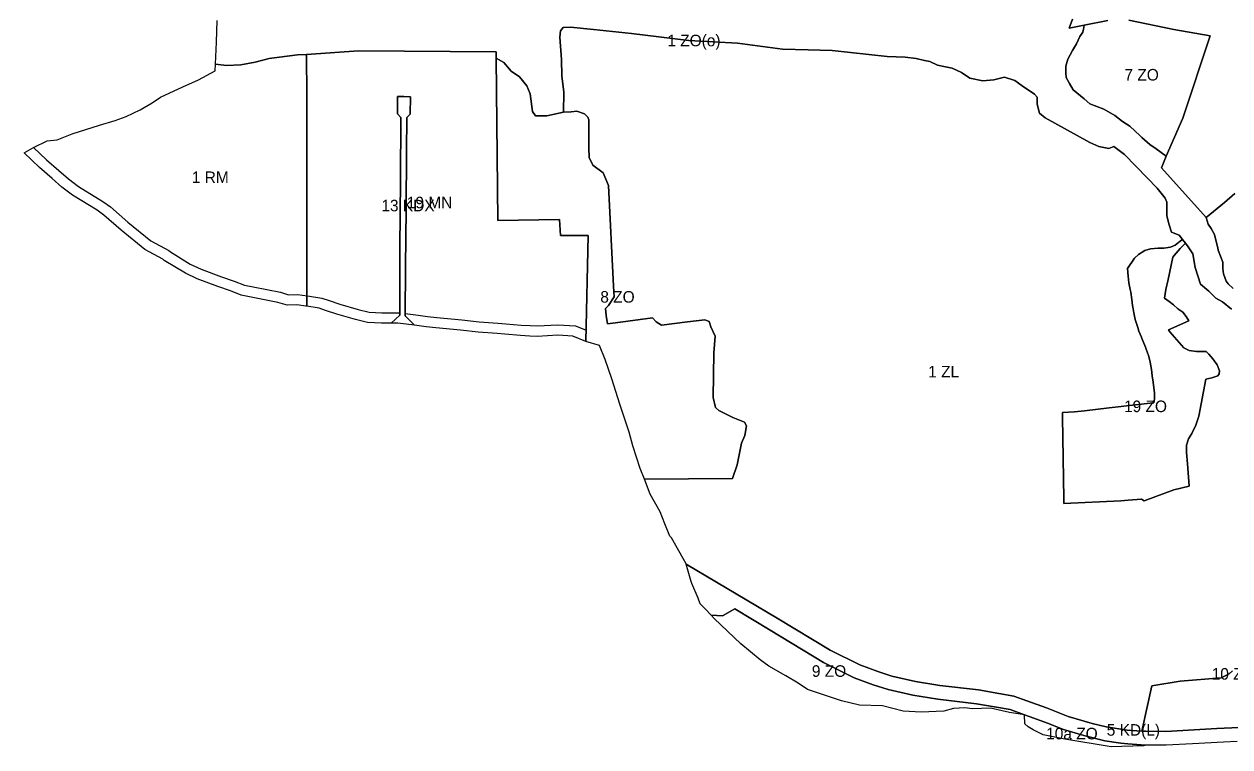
# Model space of a CAD drawing. Extents: x 7418056 to 7420315, y 5537846 to 5539505.
# Drawn here: x 7418283 to 7419326, y 5537849 to 5538474 of the extents above; entities that cross this region are included whole.
import ezdxf

# ---------------------------------------------------------------- set-up
doc = ezdxf.new("R2010")
doc.units = 0
for name, color, linetype in [('linie_rozgraniczajace', 7, 'Continuous'), ('linie_zabudowy_nieprzekraczalne', 7, 'Continuous'), ('oznaczenia_przeznaczen', 7, 'Continuous')]:
    doc.layers.add(name, color=color, linetype=linetype)

msp = doc.modelspace()

# ---------------------------------------------------------------- linework, layer by layer
at = {"layer": 'linie_rozgraniczajace'}
for points in [[(7418448.73, 5538439.82), (7418449.78, 5538458.94), (7418450.38, 5538477.48)], [(7419190.15, 5538478.7), (7419187.23, 5538471.09), (7419200.36, 5538473.67), (7419199.78, 5538469.97), (7419199.04, 5538467.44), (7419196.49, 5538463.7), (7419193.79, 5538457.39), (7419190.18, 5538451.63), (7419186.05, 5538444.07), (7419184.52, 5538438.1), (7419184.45, 5538432.48), (7419184.62, 5538428.34), (7419187.49, 5538423.15), (7419190.67, 5538417.66), (7419200.24, 5538409.93), (7419205.16, 5538405.41), (7419217.18, 5538400.86), (7419226.87, 5538395.35), (7419233.58, 5538390.3), (7419239.66, 5538386.11), (7419248.87, 5538377.92), (7419250.11, 5538376.49), (7419257.09, 5538370.36), (7419262.46, 5538366.49), (7419271.11, 5538360.17), (7419267.32, 5538350.24), (7419305.83, 5538307.27), (7419307.65, 5538301.56), (7419310.18, 5538297.82), (7419313.05, 5538292.61), (7419314.48, 5538286.46), (7419315.89, 5538280.9), (7419316.27, 5538278.85), (7419318.24, 5538273.9), (7419320.23, 5538268.66), (7419320.17, 5538263.04)], [(7419238.97, 5538477.94), (7419277.73, 5538469.82), (7419309.41, 5538464.3), (7419285.58, 5538393.04), (7419271.11, 5538360.17), (7419262.46, 5538366.49), (7419257.09, 5538370.36), (7419250.11, 5538376.49), (7419248.87, 5538377.92), (7419239.66, 5538386.11), (7419233.58, 5538390.3), (7419226.87, 5538395.35), (7419217.18, 5538400.86), (7419205.16, 5538405.41), (7419200.24, 5538409.93), (7419190.67, 5538417.66), (7419187.49, 5538423.15), (7419184.62, 5538428.34), (7419184.45, 5538432.48), (7419184.52, 5538438.1), (7419186.05, 5538444.07), (7419190.18, 5538451.63), (7419193.79, 5538457.39), (7419196.49, 5538463.7), (7419199.04, 5538467.44), (7419199.78, 5538469.97), (7419200.36, 5538473.67), (7419220.85, 5538477.69)], [(7419220.85, 5538477.69), (7419200.36, 5538473.67), (7419187.23, 5538471.09), (7419190.15, 5538478.7)], [(7419330.63, 5538328.03), (7419321.67, 5538320.2), (7419305.83, 5538307.27), (7419267.32, 5538350.24), (7419271.11, 5538360.17), (7419285.58, 5538393.04), (7419309.41, 5538464.3), (7419277.73, 5538469.82), (7419238.97, 5538477.94)], [(7419221.52, 5538367.05), (7419213.03, 5538368.63), (7419205.29, 5538372.05), (7419166.47, 5538393.45), (7419161.72, 5538397.53), (7419159.55, 5538405.3), (7419159.77, 5538411.27), (7419157.24, 5538413.96), (7419146.58, 5538421.01), (7419140.28, 5538425.6), (7419131.34, 5538428.7), (7419122.11, 5538426.27), (7419112.52, 5538425.49), (7419101.32, 5538427.87), (7419094.06, 5538432.58), (7419086.14, 5538436.39), (7419078.82, 5538437.85), (7419073.38, 5538438.91), (7419066.88, 5538442.18), (7419062.24, 5538443.04), (7419054.98, 5538444.74), (7419045.35, 5538445.95), (7419029.75, 5538446.52), (7418982.41, 5538451.77), (7418961.63, 5538452.13), (7418939.46, 5538452.92), (7418900.31, 5538458.03), (7418858.23, 5538460.21), (7418808.59, 5538466.36), (7418775.81, 5538469.78), (7418756.06, 5538471.84), (7418749.6, 5538471.58), (7418747.34, 5538468.55), (7418746.66, 5538463.07), (7418748.22, 5538443.91), (7418748.45, 5538429.86), (7418750.22, 5538415.52), (7418749.97, 5538398.36), (7418735.34, 5538395.21), (7418725.7, 5538395.27), (7418723.06, 5538399.02), (7418720.98, 5538414.29), (7418718.19, 5538421.18), (7418711.86, 5538428.95), (7418704.66, 5538433.66), (7418698.32, 5538441.42), (7418691.58, 5538445.1), (7418691.53, 5538450.4), (7418572.41, 5538451.25), (7418527.44, 5538448.19), (7418519.84, 5538447.96), (7418495.11, 5538444.7), (7418483.21, 5538441.7), (7418470.77, 5538439.19), (7418458.25, 5538438.69), (7418448.73, 5538439.82)], [(7418746.66, 5538463.07), (7418747.34, 5538468.55), (7418749.6, 5538471.58), (7418756.06, 5538471.84), (7418775.81, 5538469.78), (7418808.59, 5538466.36), (7418858.23, 5538460.21), (7418900.31, 5538458.03), (7418939.46, 5538452.92), (7418961.63, 5538452.13), (7418982.41, 5538451.77), (7419029.75, 5538446.52), (7419045.35, 5538445.95), (7419054.98, 5538444.74), (7419062.24, 5538443.04), (7419066.88, 5538442.18), (7419073.38, 5538438.91), (7419078.82, 5538437.85), (7419086.14, 5538436.39), (7419094.06, 5538432.58), (7419101.32, 5538427.87), (7419112.52, 5538425.49), (7419122.11, 5538426.27), (7419131.34, 5538428.7), (7419140.28, 5538425.6), (7419146.58, 5538421.01), (7419157.24, 5538413.96), (7419159.77, 5538411.27), (7419159.55, 5538405.3), (7419161.72, 5538397.53), (7419166.47, 5538393.45), (7419205.29, 5538372.05), (7419213.03, 5538368.63), (7419221.52, 5538367.05), (7419226.08, 5538368.5), (7419235.21, 5538361.66), (7419254.76, 5538341.44), (7419263.52, 5538332.51), (7419270.32, 5538323.95), (7419271.76, 5538320.37), (7419271.93, 5538308.59), (7419273.82, 5538301.01), (7419275.72, 5538294.7), (7419282.41, 5538291.89), (7419285.37, 5538288.17), (7419283.26, 5538286.72), (7419278.92, 5538283.32), (7419275.08, 5538281.53), (7419269.35, 5538280.71), (7419264.38, 5538280.76), (7419257.75, 5538280.26), (7419252.87, 5538278.73), (7419247.17, 5538275.23), (7419243.87, 5538272.1), (7419237.91, 5538263.27), (7419238.39, 5538256.42), (7419238.82, 5538250.61), (7419240.14, 5538245.02), (7419240.7, 5538242.61), (7419241.65, 5538236.35), (7419242.24, 5538231.09), (7419242.56, 5538228.3), (7419243.35, 5538224.67), (7419244.43, 5538219.03), (7419246.63, 5538212.24), (7419247.59, 5538208.86), (7419249.82, 5538203.89), (7419250.02, 5538203.45), (7419253.49, 5538195.02), (7419255.51, 5538189.42), (7419255.92, 5538188.3), (7419257.48, 5538182.03), (7419258.61, 5538175.84), (7419259.11, 5538170.36), (7419260.04, 5538164.92), (7419261.04, 5538155.35), (7419261.04, 5538150.49), (7419260.44, 5538146.94), (7419257.44, 5538146.79), (7419244.66, 5538145.2), (7419236.98, 5538144.24), (7419232.43, 5538143.73), (7419221.8, 5538142.53), (7419200.55, 5538140.14), (7419192.05, 5538139.18), (7419181.61, 5538138.61), (7419181.67, 5538134.61), (7419182.76, 5538063.87), (7419182.82, 5538059.86), (7419232.07, 5538062.32), (7419238.28, 5538062.68), (7419249.93, 5538063.78), (7419252.23, 5538062.14), (7419277.94, 5538071.77), (7419291.04, 5538074.98), (7419289.59, 5538094.23), (7419288.8, 5538104.14), (7419288.89, 5538110.32), (7419290.48, 5538115.86), (7419293.56, 5538120.49)], [(7418980.54, 5537932.96), (7418934.81, 5537960.77), (7418856.13, 5538007.51), (7418855.93, 5538007.87), (7418843.31, 5538030.31), (7418841.76, 5538031.54), (7418837.61, 5538042.43), (7418833.44, 5538052.58), (7418824.78, 5538067.93), (7418819.94, 5538080.93), (7418896.14, 5538081.39), (7418900.09, 5538093.38), (7418903.77, 5538112), (7418906.85, 5538118.69), (7418908.28, 5538127.08), (7418906.51, 5538130.29), (7418896.48, 5538134.27), (7418884.16, 5538140.34), (7418881.32, 5538142.96), (7418879.32, 5538151.64), (7418879.8, 5538190.33), (7418881.02, 5538204.49), (7418877.32, 5538212.73), (7418875.83, 5538217.29), (7418872.08, 5538218.62), (7418857.12, 5538217.1), (7418834.54, 5538214.14), (7418829.99, 5538216.91), (7418826.89, 5538220.48), (7418794.88, 5538216.13), (7418787.9, 5538215.2), (7418786.86, 5538222.55), (7418786.3, 5538228.4), (7418788.92, 5538231.24), (7418793.59, 5538238.56), (7418793.12, 5538247.99), (7418788.74, 5538334.83), (7418784.06, 5538345.73), (7418775.15, 5538352.39), (7418771.95, 5538359.16), (7418771.78, 5538367.42), (7418771.86, 5538391.74), (7418770.82, 5538394.04), (7418768.18, 5538396.8), (7418761.49, 5538399.16), (7418756.54, 5538398.63), (7418749.97, 5538398.36), (7418750.22, 5538415.52), (7418748.45, 5538429.86), (7418748.22, 5538443.91), (7418746.66, 5538463.07)], [(7419327.67, 5538227.89), (7419319.98, 5538234.34), (7419314.08, 5538237.53), (7419308.1, 5538243.54), (7419301.07, 5538249.51), (7419296.31, 5538263.91), (7419294.27, 5538275.81), (7419290.37, 5538281.91), (7419287.95, 5538284.94), (7419285.37, 5538288.17), (7419282.41, 5538291.89), (7419275.72, 5538294.7), (7419273.82, 5538301.01), (7419271.93, 5538308.59), (7419271.76, 5538320.37), (7419270.32, 5538323.95), (7419263.52, 5538332.51), (7419254.76, 5538341.44), (7419235.21, 5538361.66), (7419226.08, 5538368.5), (7419221.52, 5538367.05)], [(7419329.14, 5538245.97), (7419324.84, 5538249.93), (7419323.27, 5538252.23), (7419320.94, 5538258.64), (7419320.17, 5538263.04), (7419320.23, 5538268.66), (7419318.24, 5538273.9), (7419316.27, 5538278.85), (7419315.89, 5538280.9), (7419314.48, 5538286.46), (7419313.05, 5538292.61), (7419310.18, 5538297.82), (7419307.65, 5538301.56), (7419305.83, 5538307.27), (7419321.67, 5538320.2), (7419330.63, 5538328.03)], [(7419293.56, 5538120.49), (7419297.02, 5538127.53), (7419299.38, 5538135.36), (7419305.44, 5538167.57), (7419310.6, 5538168.61), (7419315.91, 5538170.23), (7419317.03, 5538172.03), (7419317.31, 5538174.54), (7419315.36, 5538179.93), (7419311.68, 5538184.88), (7419308.24, 5538189.11), (7419305.73, 5538191.44), (7419297.45, 5538191.37), (7419291.24, 5538192.26), (7419286.39, 5538194.41), (7419274.45, 5538208.49), (7419273.15, 5538210.02), (7419290.92, 5538217.99), (7419288.51, 5538221.7), (7419285.54, 5538225.34), (7419281.31, 5538228.15), (7419277.58, 5538231.66), (7419273.77, 5538234.64), (7419269.8, 5538237.44), (7419270.8, 5538245), (7419273.04, 5538253.69), (7419277.09, 5538272.99), (7419278.06, 5538274.52), (7419283.33, 5538280.54), (7419287.95, 5538284.94), (7419290.37, 5538281.91), (7419294.27, 5538275.81), (7419296.31, 5538263.91), (7419301.07, 5538249.51), (7419308.1, 5538243.54), (7419314.08, 5538237.53), (7419319.98, 5538234.34), (7419327.67, 5538227.89)], [(7419320.17, 5538263.04), (7419320.94, 5538258.64), (7419323.27, 5538252.23), (7419324.84, 5538249.93), (7419329.14, 5538245.97)], [(7419332.73, 5537854.1), (7419320.89, 5537853.5), (7419293.94, 5537852.05), (7419271.36, 5537850.8), (7419253.58, 5537850.83), (7419249.55, 5537851.13), (7419238.21, 5537851.93), (7419232, 5537852.69), (7419218.26, 5537854.66), (7419200, 5537859.2), (7419182.4, 5537864.47), (7419168.49, 5537870), (7419156.89, 5537874.27), (7419148.78, 5537877.11), (7419136.16, 5537881.67), (7419124.44, 5537883.87), (7419107.23, 5537886.75), (7419073.7, 5537890.67), (7419052.01, 5537894.29), (7419030.63, 5537898.97), (7419017.78, 5537903.17), (7419001.32, 5537909.25), (7418974.75, 5537922.44), (7418928.61, 5537950.49), (7418898.04, 5537968.75), (7418887.37, 5537962.66), (7418877.63, 5537963.36), (7418872.41, 5537968.93), (7418868.07, 5537973.15), (7418866.42, 5537978.03), (7418860.83, 5537990.68), (7418860.09, 5537993.34), (7418856.13, 5538007.51), (7418934.81, 5537960.77), (7418980.54, 5537932.96), (7419006.09, 5537920.29), (7419021.73, 5537914.51), (7419033.78, 5537910.55), (7419054.28, 5537906.07), (7419075.38, 5537902.54), (7419108.92, 5537898.63), (7419126.53, 5537895.68), (7419139.37, 5537893.28), (7419150.65, 5537889.13), (7419167.77, 5537883.21), (7419186.4, 5537875.79), (7419207.33, 5537869.53), (7419219.31, 5537866.63), (7419237.54, 5537864.01), (7419250.25, 5537863.11), (7419253.32, 5537862.89), (7419271.06, 5537862.8), (7419315.06, 5537865.23), (7419347.25, 5537866.84)], [(7419328.74, 5537915.33), (7419325.77, 5537912.5), (7419318.81, 5537909.18), (7419283.34, 5537906.26), (7419258.85, 5537902.17), (7419250.25, 5537863.11), (7419237.54, 5537864.01), (7419219.31, 5537866.63), (7419207.33, 5537869.53), (7419186.4, 5537875.79), (7419167.77, 5537883.21), (7419150.65, 5537889.13), (7419139.37, 5537893.28), (7419126.53, 5537895.68), (7419108.92, 5537898.63), (7419075.38, 5537902.54), (7419054.28, 5537906.07), (7419033.78, 5537910.55), (7419021.73, 5537914.51), (7419006.09, 5537920.29), (7418980.54, 5537932.96)], [(7419347.25, 5537866.84), (7419315.06, 5537865.23), (7419271.06, 5537862.8), (7419253.32, 5537862.89), (7419250.25, 5537863.11), (7419258.85, 5537902.17), (7419283.34, 5537906.26), (7419318.81, 5537909.18), (7419325.77, 5537912.5), (7419328.74, 5537915.33)]]:
    msp.add_lwpolyline(points, dxfattribs=at)
for points in [[(7418283.26, 5538363.1), (7418291.34, 5538367.72), (7418303.34, 5538373.67), (7418311.73, 5538374.28), (7418324.88, 5538379.67), (7418348.42, 5538387.19), (7418362.09, 5538390.99), (7418371.43, 5538394.67), (7418383.57, 5538400.46), (7418393.95, 5538406.53), (7418401.1, 5538411.22), (7418420.7, 5538420.16), (7418434.15, 5538426.26), (7418448.41, 5538434.06), (7418448.73, 5538439.82), (7418458.25, 5538438.69), (7418470.77, 5538439.19), (7418483.21, 5538441.7), (7418495.11, 5538444.7), (7418519.84, 5538447.96), (7418527.44, 5538448.19), (7418527.96, 5538412.34), (7418527.86, 5538230.55), (7418527.11, 5538230.67), (7418519.2, 5538231.59), (7418510.89, 5538231.48), (7418502.89, 5538233.77), (7418479.64, 5538238.34), (7418471.17, 5538239.97), (7418461.88, 5538243.83), (7418450.91, 5538247.46), (7418432.89, 5538254.27), (7418422.75, 5538259.01), (7418404.56, 5538270.09), (7418403.32, 5538271.12), (7418387.72, 5538279.63), (7418367.27, 5538296.25), (7418352.3, 5538309.34), (7418346.49, 5538313.57), (7418325.2, 5538326.63), (7418315.86, 5538333.55), (7418307.49, 5538341), (7418296.5, 5538350.36)], [(7418527.86, 5538230.55), (7418527.96, 5538412.34), (7418527.44, 5538448.19), (7418572.41, 5538451.25), (7418691.53, 5538450.4), (7418691.58, 5538445.1), (7418692.98, 5538304.59), (7418746.51, 5538305.4), (7418747.17, 5538291.63), (7418771.22, 5538291.71), (7418769.33, 5538200.07), (7418758.09, 5538204.64), (7418744.87, 5538205.53), (7418727.09, 5538204.4), (7418720.7, 5538204.73), (7418712.6, 5538205.15), (7418699.01, 5538206.41), (7418692.37, 5538207.02), (7418676.01, 5538208.13), (7418660.91, 5538209.92), (7418639.42, 5538211.79), (7418631.16, 5538212.78), (7418620.93, 5538214.24), (7418613, 5538222.17), (7418613.27, 5538264.45), (7418613.66, 5538314.44), (7418614.05, 5538364.4), (7418614.26, 5538393.7), (7418617.32, 5538396.73), (7418617.45, 5538411.7), (7418611.89, 5538411.81), (7418606.4, 5538412.02), (7418606.27, 5538396.85), (7418609.27, 5538393.85), (7418608.85, 5538339.23), (7418608.36, 5538281.2), (7418608.19, 5538222.7), (7418600.78, 5538215.88), (7418592.54, 5538215.88), (7418580.42, 5538216.51), (7418569.97, 5538218.93), (7418553.82, 5538223.6), (7418544.05, 5538226.89), (7418538.63, 5538228.86)], [(7418692.98, 5538304.59), (7418691.58, 5538445.1), (7418698.32, 5538441.42), (7418704.66, 5538433.66), (7418711.86, 5538428.95), (7418718.19, 5538421.18), (7418720.98, 5538414.29), (7418723.06, 5538399.02), (7418725.7, 5538395.27), (7418735.34, 5538395.21), (7418749.97, 5538398.36), (7418756.54, 5538398.63), (7418761.49, 5538399.16), (7418768.18, 5538396.8), (7418770.82, 5538394.04), (7418771.86, 5538391.74), (7418771.78, 5538367.42), (7418771.95, 5538359.16), (7418775.15, 5538352.39), (7418784.06, 5538345.73), (7418788.74, 5538334.83), (7418793.12, 5538247.99), (7418793.59, 5538238.56), (7418788.92, 5538231.24), (7418786.3, 5538228.4), (7418786.86, 5538222.55), (7418787.9, 5538215.2), (7418794.88, 5538216.13), (7418826.89, 5538220.48), (7418829.99, 5538216.91), (7418834.54, 5538214.14), (7418857.12, 5538217.1), (7418872.08, 5538218.62), (7418875.83, 5538217.29), (7418877.32, 5538212.73), (7418881.02, 5538204.49), (7418879.8, 5538190.33), (7418879.32, 5538151.64), (7418881.32, 5538142.96), (7418884.16, 5538140.34), (7418896.48, 5538134.27), (7418906.51, 5538130.29), (7418908.28, 5538127.08), (7418906.85, 5538118.69), (7418903.77, 5538112), (7418900.09, 5538093.38), (7418896.14, 5538081.39), (7418819.94, 5538080.93), (7418816.2, 5538090.08), (7418809.97, 5538109.86), (7418806.66, 5538121.56), (7418798.52, 5538145.73), (7418791.56, 5538167.76), (7418786.02, 5538184.35), (7418780.9, 5538196.67), (7418769.33, 5538200.07), (7418771.22, 5538291.71), (7418747.17, 5538291.63), (7418746.51, 5538305.4)], [(7418600.78, 5538215.88), (7418608.19, 5538222.7), (7418608.36, 5538281.2), (7418608.85, 5538339.23), (7418609.27, 5538393.85), (7418606.27, 5538396.85), (7418606.4, 5538412.02), (7418611.89, 5538411.81), (7418617.45, 5538411.7), (7418617.32, 5538396.73), (7418614.26, 5538393.7), (7418614.05, 5538364.4), (7418613.66, 5538314.44), (7418613.27, 5538264.45), (7418613, 5538222.17), (7418620.93, 5538214.24), (7418606.48, 5538215.89)], [(7419182.82, 5538059.86), (7419182.76, 5538063.87), (7419181.67, 5538134.61), (7419181.61, 5538138.61), (7419192.05, 5538139.18), (7419200.55, 5538140.14), (7419221.8, 5538142.53), (7419232.43, 5538143.73), (7419236.98, 5538144.24), (7419244.66, 5538145.2), (7419257.44, 5538146.79), (7419260.44, 5538146.94), (7419261.04, 5538150.49), (7419261.04, 5538155.35), (7419260.04, 5538164.92), (7419259.11, 5538170.36), (7419258.61, 5538175.84), (7419257.48, 5538182.03), (7419255.92, 5538188.3), (7419255.51, 5538189.42), (7419253.49, 5538195.02), (7419250.02, 5538203.45), (7419249.82, 5538203.89), (7419247.59, 5538208.86), (7419246.63, 5538212.24), (7419244.43, 5538219.03), (7419243.35, 5538224.67), (7419242.56, 5538228.3), (7419242.24, 5538231.09), (7419241.65, 5538236.35), (7419240.7, 5538242.61), (7419240.14, 5538245.02), (7419238.82, 5538250.61), (7419238.39, 5538256.42), (7419237.91, 5538263.27), (7419243.87, 5538272.1), (7419247.17, 5538275.23), (7419252.87, 5538278.73), (7419257.75, 5538280.26), (7419264.38, 5538280.76), (7419269.35, 5538280.71), (7419275.08, 5538281.53), (7419278.92, 5538283.32), (7419283.26, 5538286.72), (7419285.37, 5538288.17), (7419287.95, 5538284.94), (7419283.33, 5538280.54), (7419278.06, 5538274.52), (7419277.09, 5538272.99), (7419273.04, 5538253.69), (7419270.8, 5538245), (7419269.8, 5538237.44), (7419273.77, 5538234.64), (7419277.58, 5538231.66), (7419281.31, 5538228.15), (7419285.54, 5538225.34), (7419288.51, 5538221.7), (7419290.92, 5538217.99), (7419273.15, 5538210.02), (7419274.45, 5538208.49), (7419286.39, 5538194.41), (7419291.24, 5538192.26), (7419297.45, 5538191.37), (7419305.73, 5538191.44), (7419308.24, 5538189.11), (7419311.68, 5538184.88), (7419315.36, 5538179.93), (7419317.31, 5538174.54), (7419317.03, 5538172.03), (7419315.91, 5538170.23), (7419310.6, 5538168.61), (7419305.44, 5538167.57), (7419299.38, 5538135.36), (7419297.02, 5538127.53), (7419293.56, 5538120.49), (7419290.48, 5538115.86), (7419288.89, 5538110.32), (7419288.8, 5538104.14), (7419289.59, 5538094.23), (7419291.04, 5538074.98), (7419277.94, 5538071.77), (7419252.23, 5538062.14), (7419249.93, 5538063.78), (7419238.28, 5538062.68), (7419232.07, 5538062.32)], [(7418877.63, 5537963.36), (7418887.37, 5537962.66), (7418898.04, 5537968.75), (7418928.61, 5537950.49), (7418974.75, 5537922.44), (7419001.32, 5537909.25), (7419017.78, 5537903.17), (7419030.63, 5537898.97), (7419052.01, 5537894.29), (7419073.7, 5537890.67), (7419107.23, 5537886.75), (7419124.44, 5537883.87), (7419136.16, 5537881.67), (7419148.78, 5537877.11), (7419135.77, 5537879.2), (7419119.39, 5537882.8), (7419103.81, 5537882.34), (7419096.92, 5537883.3), (7419087.24, 5537882.6), (7419078.91, 5537880.34), (7419059.2, 5537879.33), (7419043.61, 5537880.45), (7419025.7, 5537885.05), (7419005.93, 5537885.54), (7418990.24, 5537889.29), (7418960.98, 5537899.15), (7418952.91, 5537904.56), (7418942.08, 5537910.84), (7418927.61, 5537919.32), (7418919.9, 5537924.58), (7418903.19, 5537938.47), (7418880.27, 5537960.55)], [(7419148.9, 5537869.49), (7419148.78, 5537877.11), (7419156.89, 5537874.27), (7419168.49, 5537870), (7419182.4, 5537864.47), (7419200, 5537859.2), (7419218.26, 5537854.66), (7419232, 5537852.69), (7419238.21, 5537851.93), (7419249.55, 5537851.13), (7419253.58, 5537850.83), (7419251.55, 5537850.37), (7419223.73, 5537849.43), (7419183.66, 5537856.11), (7419164.94, 5537859.73), (7419156.03, 5537864.25), (7419151.9, 5537866.65)]]:
    msp.add_lwpolyline(points, close=True, dxfattribs=at)
at = {"layer": 'linie_zabudowy_nieprzekraczalne'}
for points in [[(7418291.4, 5538367.76), (7418302.54, 5538357.04), (7418313.4, 5538347.8), (7418321.55, 5538340.54), (7418330.24, 5538334.1), (7418351.5, 5538321.06), (7418357.93, 5538316.38), (7418373.07, 5538303.14), (7418392.75, 5538287.14), (7418408.42, 5538278.59), (7418409.82, 5538277.42), (7418427.01, 5538266.95), (7418436.39, 5538262.58), (7418453.92, 5538255.95), (7418465.02, 5538252.27), (7418473.78, 5538248.63), (7418481.36, 5538247.18), (7418505, 5538242.53), (7418512.09, 5538240.5), (7418519.66, 5538240.6), (7418528.33, 5538239.59), (7418540.89, 5538237.62), (7418547.03, 5538235.39), (7418556.51, 5538232.19), (7418572.24, 5538227.64), (7418581.68, 5538225.46), (7418592.77, 5538224.88), (7418606.99, 5538224.89), (7418608.19, 5538224.75)], [(7418613.02, 5538224.2), (7418622.08, 5538223.17), (7418632.33, 5538221.71), (7418640.34, 5538220.74), (7418661.83, 5538218.88), (7418676.85, 5538217.1), (7418693.09, 5538216), (7418699.85, 5538215.37), (7418713.25, 5538214.13), (7418721.16, 5538213.72), (7418727.04, 5538213.42), (7418744.89, 5538214.56), (7418760.14, 5538213.52), (7418769.59, 5538209.68)]]:
    msp.add_lwpolyline(points, dxfattribs=at)

# ---------------------------------------------------------------- texts
at = {"layer": 'oznaczenia_przeznaczen'}
for s, p in [('1 ZO(o)', (7418839.69, 5538455.29)), ('7 ZO', (7419235.15, 5538425.7)), ('1 RM', (7418428.35, 5538337.03)), ('13 KDX', (7418592.31, 5538312.56)), ('19 MN', (7418614.34, 5538315.2)), ('8 ZO', (7418781.72, 5538233.61)), ('1 ZL', (7419065.35, 5538168.92)), ('19 ZO', (7419234.77, 5538138.94)), ('9 ZO', (7418964.73, 5537910.01)), ('10 ZO', (7419310.61, 5537907.56)), ('5 KD(L)', (7419219.82, 5537859.09)), ('10a ZO', (7419167.4, 5537855.93))]:
    msp.add_text(s, height=10, dxfattribs=at).set_placement(p)

doc.saveas('drawing.dxf')
